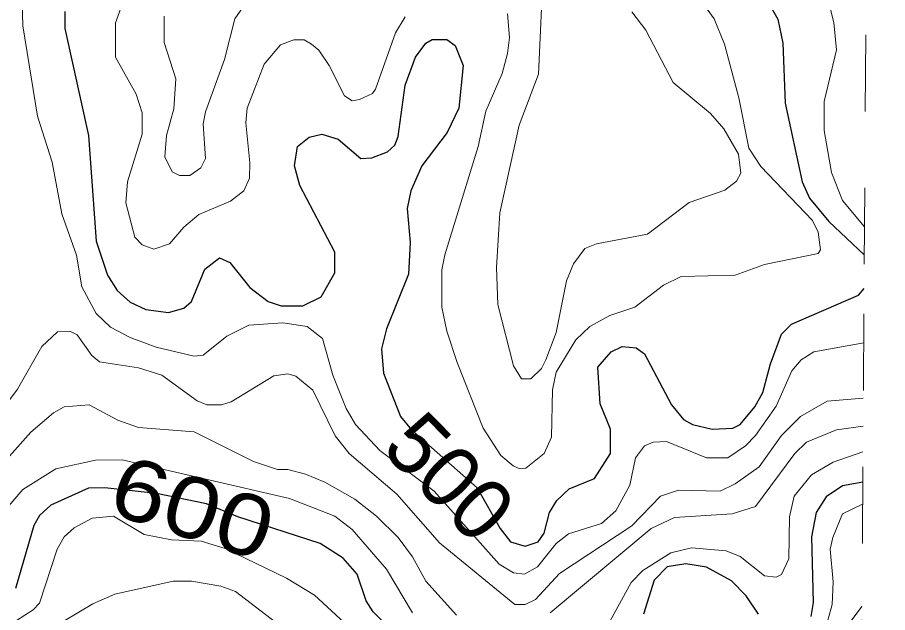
# Model space of a CAD drawing. Extents: x 577 to 602.9, y 7483.8 to 7511.6.
# Drawn here: x 601.59 to 602.727, y 7486.144 to 7486.922 of the extents above; entities that cross this region are included whole.
import ezdxf
from ezdxf.enums import TextEntityAlignment as Align

# ---------------------------------------------------------------- set-up
doc = ezdxf.new("R2010")
doc.units = 0
doc.header["$LTSCALE"] = 0.032
doc.linetypes.add('SHORT_DASHED', pattern=[2.7, 1.5, -1.2])
for name, color, linetype, lineweight in [('1', 7, 'Continuous', 25), ('2', 7, 'Continuous', 13), ('62', 7, 'SHORT_DASHED', 13)]:
    doc.layers.add(name, color=color, linetype=linetype, lineweight=lineweight)
doc.layers.add('61', color=7, linetype='Continuous')

msp = doc.modelspace()

# ---------------------------------------------------------------- linework, layer by layer
at = {"layer": '1'}
for points in [[(602.702, 7487.4534), (602.6725, 7487.4066), (602.6685, 7487.3867), (602.6622, 7487.2785), (602.659, 7487.2555), (602.6518, 7487.2356), (602.6335, 7487.2086), (602.5842, 7487.1656), (602.5437, 7487.1219), (602.5182, 7487.0861), (602.5008, 7487.0503), (602.5008, 7487.0344), (602.5111, 7487.0122), (602.5564, 7486.9676), (602.5835, 7486.9199), (602.5898, 7486.8889), (602.593, 7486.8102), (602.6153, 7486.7076), (602.6248, 7486.6861), (602.6501, 7486.6557), (602.6963, 7486.6118)], [(601.6523, 7486.9303), (601.6523, 7486.908), (601.6833, 7486.768), (601.6929, 7486.6297), (601.708, 7486.5852), (601.7207, 7486.5653), (601.7374, 7486.5502), (601.7581, 7486.5406), (601.7875, 7486.5366), (601.8074, 7486.5422), (601.8177, 7486.551), (601.8352, 7486.5931), (601.8543, 7486.6082), (601.8678, 7486.6019), (601.894, 7486.5693), (601.9179, 7486.551), (601.9346, 7486.5454), (601.9632, 7486.5454), (601.9871, 7486.5573), (602.0046, 7486.5883), (602.0046, 7486.6154), (601.9592, 7486.7028), (601.9521, 7486.7283), (601.9561, 7486.7537), (601.9712, 7486.7657), (601.9879, 7486.7696), (602.0093, 7486.7633), (602.0388, 7486.7378), (602.0531, 7486.7386), (602.0737, 7486.7466), (602.0833, 7486.7553), (602.0873, 7486.7665), (602.0968, 7486.834), (602.1103, 7486.8706), (602.1238, 7486.8889), (602.1318, 7486.8937), (602.1509, 7486.8937), (602.162, 7486.8857), (602.1723, 7486.8595), (602.1668, 7486.8038), (602.1517, 7486.772), (602.1183, 7486.7283), (602.104, 7486.6957), (602.0992, 7486.6726), (602.1032, 7486.6281), (602.1008, 7486.5867), (602.0722, 7486.5152), (602.0658, 7486.4889), (602.0682, 7486.4571), (602.0904, 7486.4007), (602.1048, 7486.3832), (602.1908, 7486.3075), (602.2209, 7486.2544), (602.2344, 7486.2369), (602.2535, 7486.2313), (602.2702, 7486.2369), (602.2781, 7486.248), (602.2853, 7486.275), (602.2948, 7486.2909), (602.3107, 7486.306), (602.3441, 7486.3196), (602.3648, 7486.3522), (602.3648, 7486.384), (602.3513, 7486.4174)], [(602.3513, 7486.4174), (602.3481, 7486.4651), (602.3656, 7486.485), (602.3799, 7486.4921), (602.3982, 7486.4905), (602.4093, 7486.4826), (602.4443, 7486.4158), (602.4602, 7486.3967), (602.4721, 7486.3903), (602.4976, 7486.384), (602.5246, 7486.3856), (602.5342, 7486.3903), (602.5532, 7486.4134), (602.5636, 7486.4319), (602.5736, 7486.4697), (602.5883, 7486.5082), (602.6014, 7486.5214), (602.6889, 7486.5592), (602.696, 7486.568)], [(602.1389, 7486.0611), (602.0547, 7486.1454), (602.0459, 7486.1597), (602.034, 7486.1947), (602.0157, 7486.2154), (601.9855, 7486.2345), (601.8781, 7486.2695), (601.8373, 7486.2866), (601.7719, 7486.2999), (601.7043, 7486.3076), (601.6833, 7486.3068), (601.634, 7486.2846), (601.6189, 7486.2711), (601.6117, 7486.2583), (601.5879, 7486.1756)], [(602.6943, 7486.3148), (602.668, 7486.31), (602.6463, 7486.2957), (602.6335, 7486.275), (602.6272, 7486.2432), (602.6296, 7486.1574), (602.6264, 7486.1391)], [(602.558, 7486.1422), (602.5421, 7486.1661), (602.523, 7486.186), (602.4904, 7486.2035), (602.4634, 7486.2082), (602.4387, 7486.2043), (602.422, 7486.1868), (602.4077, 7486.1422)]]:
    msp.add_lwpolyline(points, dxfattribs=at)
at = {"layer": '2'}
for points in [[(602.7004, 7487.2202), (602.663, 7487.1481), (602.6176, 7487.1068), (602.6025, 7487.0861), (602.5962, 7487.0686), (602.6025, 7487.0217), (602.6502, 7486.9398), (602.6566, 7486.9159), (602.6598, 7486.8802), (602.6439, 7486.8126), (602.6439, 7486.7744), (602.6534, 7486.7195), (602.6677, 7486.683), (602.6965, 7486.6485)], [(602.0968, 7486.9231), (602.0841, 7486.9024), (602.0578, 7486.8285), (602.0539, 7486.8229), (602.0372, 7486.815), (602.0276, 7486.8134), (602.0173, 7486.8197), (601.9974, 7486.8595), (601.9839, 7486.8794), (601.9743, 7486.8873), (601.9648, 7486.8929), (601.9513, 7486.8929), (601.9338, 7486.8865), (601.9123, 7486.8611), (601.8901, 7486.8038), (601.8885, 7486.7847), (601.894, 7486.7323), (601.8932, 7486.7124), (601.8861, 7486.6957), (601.8686, 7486.6822), (601.8272, 7486.6647), (601.8074, 7486.648), (601.7891, 7486.6265), (601.7684, 7486.6193), (601.7533, 7486.6249), (601.7437, 7486.6353), (601.7318, 7486.6798), (601.7342, 7486.7076), (601.7533, 7486.7696), (601.7533, 7486.7975), (601.7453, 7486.8221), (601.7183, 7486.8706), (601.7183, 7486.9152), (601.7501, 7487.0034)], [(602.4602, 7486.9764), (602.5, 7486.9207), (602.5135, 7486.8873), (602.5326, 7486.8173), (602.5453, 7486.7513), (602.5612, 7486.7275), (602.6288, 7486.6567), (602.6359, 7486.6416), (602.6391, 7486.6186), (602.6359, 7486.6138), (602.566, 7486.5995), (602.5278, 7486.5852), (602.457, 7486.5836), (602.434, 7486.5724), (602.3966, 7486.5438), (602.364, 7486.5327), (602.3377, 7486.5184), (602.3195, 7486.5009), (602.294, 7486.4587), (602.2892, 7486.4357), (602.2876, 7486.3736), (602.2781, 7486.3522), (602.2542, 7486.3331), (602.2463, 7486.3323), (602.2376, 7486.3363), (602.2216, 7486.3498), (602.1986, 7486.3856), (602.1644, 7486.4714), (602.1509, 7486.512), (602.1445, 7486.5438), (602.1445, 7486.5923), (602.1485, 7486.6122), (602.1922, 7486.7537), (602.2018, 7486.7999), (602.2232, 7486.8492), (602.2304, 7486.8754), (602.2328, 7486.8961), (602.2304, 7486.9271)], [(601.5966, 7486.9438), (601.5974, 7486.9112), (601.6165, 7486.7935), (601.6356, 7486.7331), (601.6483, 7486.6655), (601.6674, 7486.6114), (601.6746, 7486.57), (601.6929, 7486.5351), (601.7119, 7486.5176), (601.7374, 7486.504), (601.7716, 7486.4913), (601.8209, 7486.4794), (601.8328, 7486.481), (601.8638, 7486.5056), (601.8924, 7486.52), (601.937, 7486.5231), (601.9688, 7486.5184), (601.9887, 7486.5025), (602.0022, 7486.4547), (602.0197, 7486.411), (602.0316, 7486.3903), (602.0634, 7486.3561), (602.1344, 7486.3031), (602.2193, 7486.2074), (602.2383, 7486.1963), (602.2527, 7486.1947), (602.2694, 7486.2043), (602.294, 7486.2345), (602.3099, 7486.2472), (602.3529, 7486.2607), (602.3719, 7486.2774), (602.3902, 7486.3108), (602.3974, 7486.3466), (602.4093, 7486.3625), (602.4204, 7486.3673), (602.4379, 7486.3681), (602.4904, 7486.3466), (602.5182, 7486.3466), (602.5413, 7486.3625), (602.554, 7486.376), (602.5811, 7486.4142), (602.6017, 7486.4603), (602.6137, 7486.4746), (602.6304, 7486.485), (602.6955, 7486.4968)], [(601.8901, 7486.9438), (601.8742, 7486.9207), (601.8606, 7486.8674), (601.836, 7486.7991), (601.8328, 7486.7832), (601.836, 7486.7378), (601.8296, 7486.7259), (601.8153, 7486.7156), (601.8018, 7486.7156), (601.7923, 7486.7203), (601.7827, 7486.7402), (601.7851, 7486.768), (601.7946, 7486.803), (601.797, 7486.842), (601.7819, 7486.8897), (601.7819, 7486.9239)], [(602.3926, 7486.9295), (602.4109, 7486.9056), (602.4467, 7486.8372), (602.4952, 7486.7967), (602.5127, 7486.7768), (602.5318, 7486.7434), (602.5349, 7486.7187), (602.5294, 7486.7084), (602.5143, 7486.6965), (602.4674, 7486.6806), (602.4133, 7486.6392), (602.3465, 7486.6265), (602.3314, 7486.6201), (602.3163, 7486.6003), (602.3075, 7486.578), (602.294, 7486.5104), (602.2805, 7486.4746), (602.2749, 7486.4635), (602.2606, 7486.45), (602.2487, 7486.45), (602.2383, 7486.4667), (602.2177, 7486.547), (602.2161, 7486.5955), (602.2201, 7486.6671), (602.2455, 7486.7816), (602.2709, 7486.8484), (602.2749, 7486.9342)], [(601.5481, 7486.38), (601.5903, 7486.4365), (601.6221, 7486.4921), (601.6428, 7486.5112), (601.6587, 7486.512), (601.6682, 7486.5072), (601.6873, 7486.4802), (601.6976, 7486.4722), (601.7485, 7486.4643), (601.7787, 7486.4547), (601.8249, 7486.4213), (601.8376, 7486.4158), (601.8567, 7486.4158), (601.8694, 7486.4198), (601.925, 7486.454), (601.9433, 7486.4563), (601.9537, 7486.4532), (601.9759, 7486.4349), (602.0054, 7486.3752), (602.0236, 7486.3522), (602.0857, 7486.2989), (602.1413, 7486.2353), (602.2399, 7486.155), (602.2535, 7486.155), (602.267, 7486.1613), (602.298, 7486.1955), (602.3926, 7486.2575), (602.43, 7486.2965), (602.4538, 7486.3045), (602.5079, 7486.3029), (602.5278, 7486.3124), (602.5588, 7486.3347), (602.5882, 7486.376), (602.6129, 7486.4007), (602.6479, 7486.4206), (602.695, 7486.4245)], [(602.1636, 7486.1407), (602.1238, 7486.1852), (602.1063, 7486.217), (602.0873, 7486.2424), (602.0594, 7486.2703), (602.0308, 7486.2925), (601.9918, 7486.3148), (601.9664, 7486.3251), (601.9433, 7486.3315), (601.9298, 7486.3315), (601.8988, 7486.3418), (601.8209, 7486.3808), (601.7485, 7486.3864), (601.7215, 7486.3959), (601.6841, 7486.4158), (601.6515, 7486.4134), (601.6372, 7486.4054), (601.6078, 7486.38), (601.5656, 7486.3331)], [(602.6948, 7486.388), (602.6598, 7486.3832), (602.6208, 7486.3673), (602.6057, 7486.3522), (602.554, 7486.283), (602.5238, 7486.2734), (602.4483, 7486.2687), (602.4181, 7486.2544), (602.2861, 7486.1438)], [(602.6945, 7486.3543), (602.6558, 7486.341), (602.6272, 7486.3243), (602.6049, 7486.2965), (602.5986, 7486.2695), (602.5978, 7486.2146), (602.5882, 7486.1939), (602.5811, 7486.1907), (602.566, 7486.1923), (602.5342, 7486.2178), (602.5159, 7486.2249), (602.4705, 7486.2289), (602.4435, 7486.2226), (602.4069, 7486.1995), (602.3918, 7486.1836), (602.3592, 7486.124)], [(602.1063, 7486.1438), (602.0722, 7486.2011), (602.0276, 7486.2528), (602.0046, 7486.2703), (601.9457, 7486.2933), (601.727, 7486.3442), (601.6921, 7486.3434), (601.6404, 7486.3323), (601.5974, 7486.3053), (601.5791, 7486.2838)], [(602.6447, 7486.12), (602.6542, 7486.155), (602.6558, 7486.1844), (602.6518, 7486.2273), (602.655, 7486.2424), (602.6677, 7486.2734), (602.6941, 7486.2861)], [(601.5784, 7486.1271), (601.611, 7486.1478), (601.6189, 7486.1566), (601.642, 7486.2273), (601.6515, 7486.2432), (601.6642, 7486.2552), (601.6881, 7486.2679), (601.7157, 7486.2703), (601.7557, 7486.2464), (601.7915, 7486.2393), (601.8304, 7486.2377), (601.8614, 7486.2281), (601.9417, 7486.1892), (601.9783, 7486.1669), (602.0229, 7486.1255), (602.0881, 7486.0747), (602.1, 7486.0556), (602.1095, 7486.0126), (602.127, 7485.9776)], [(601.6316, 7486.1216), (601.6889, 7486.1558), (601.7175, 7486.1685), (601.7938, 7486.1852), (601.8177, 7486.1852), (601.8559, 7486.1788), (601.875, 7486.1717), (601.9274, 7486.1319)], [(602.6598, 7486.108), (602.6932, 7486.1522)]]:
    msp.add_lwpolyline(points, dxfattribs=at)
at = {"layer": '62'}
msp.add_lwpolyline([(602.6772, 7483.7754), (602.681, 7484.3402), (602.6848, 7484.9051), (602.6886, 7485.4699), (602.6924, 7486.0347), (602.6962, 7486.5996), (602.7, 7487.1644), (602.7038, 7487.7293), (602.7076, 7488.2941), (602.7115, 7488.859), (602.7153, 7489.4238), (602.7191, 7489.9887), (602.7229, 7490.5535), (602.7267, 7491.1183)], dxfattribs=at)

# ---------------------------------------------------------------- texts
at = {"layer": '61'}
msp.add_text('500', height=0.08, rotation=314.576, dxfattribs=at).set_placement((602.1266, 7486.2936), align=Align.CENTER)
at = {"layer": '61', "width": 1.2}
msp.add_text('600', height=0.08, rotation=342.333, dxfattribs=at).set_placement((601.8068, 7486.2433), align=Align.CENTER)

doc.saveas('drawing.dxf')
